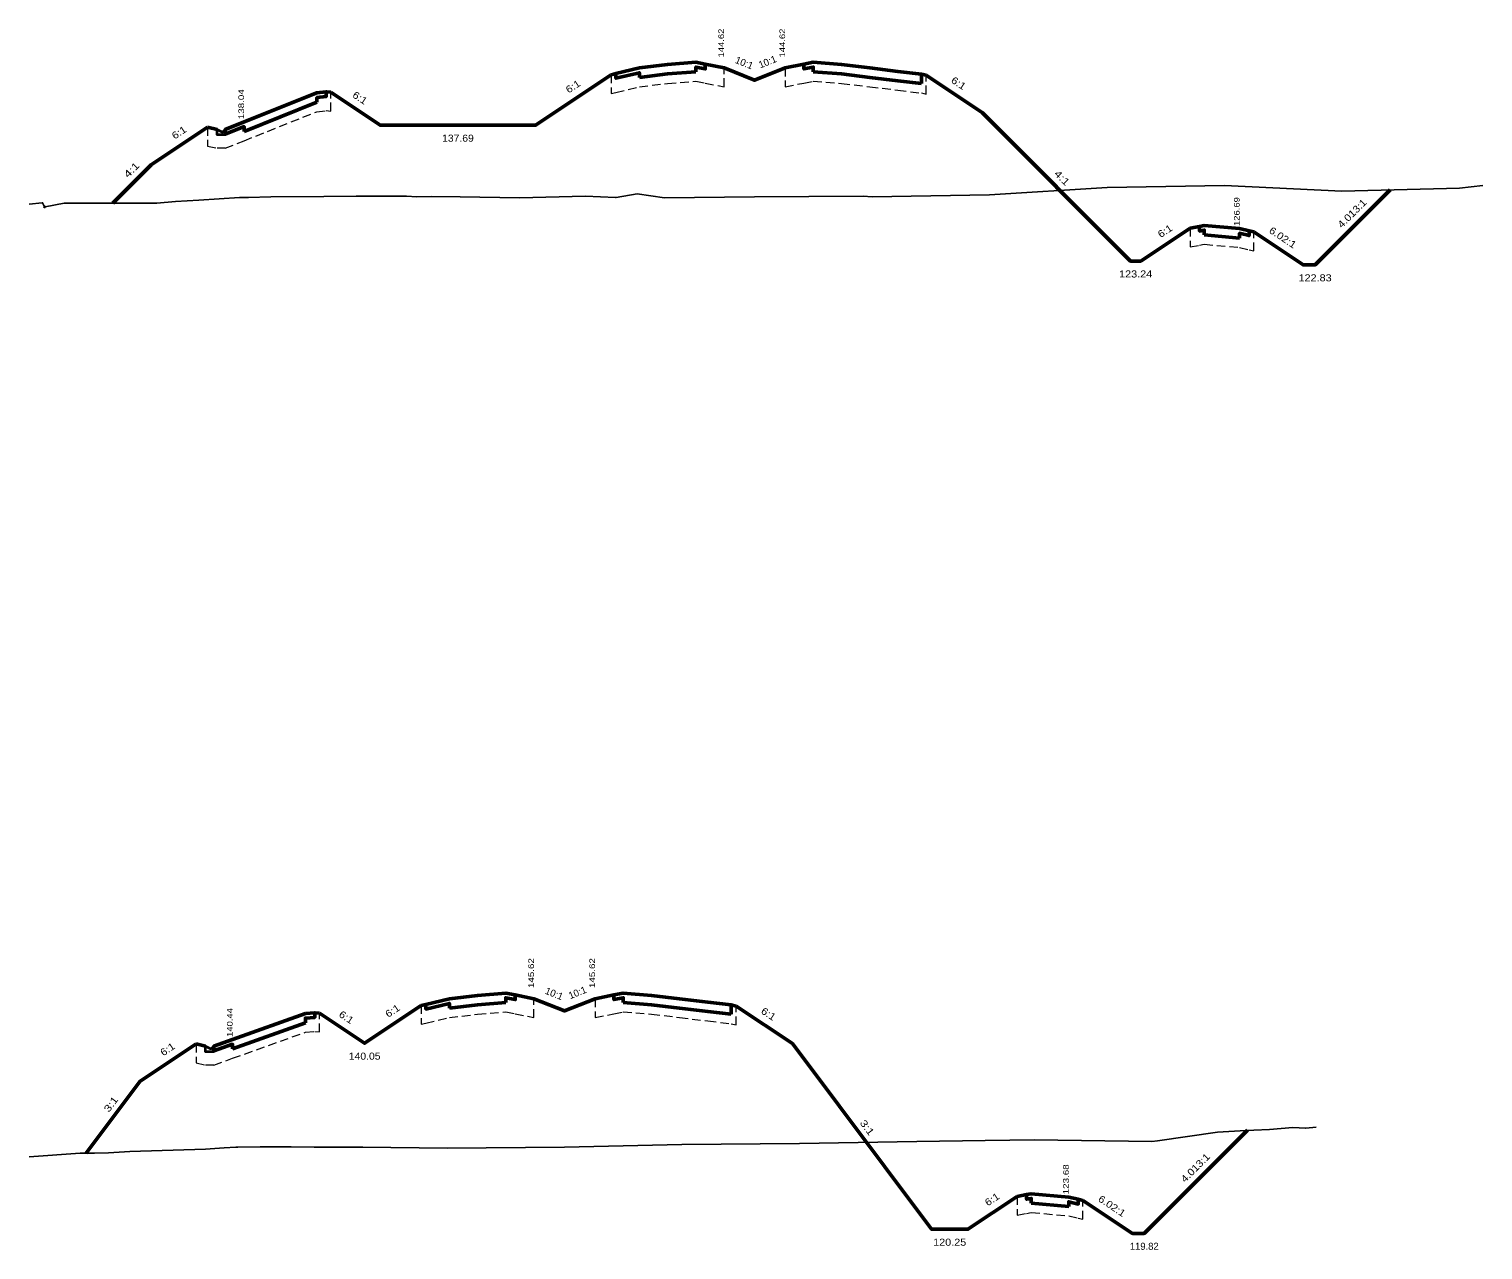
# Model space of a CAD drawing. Extents: x 72769 to 76375, y 67856 to 87579.
# Drawn here: x 72774 to 73393, y 87059 to 87579 of the extents above; entities that cross this region are included whole.
import ezdxf
from ezdxf.enums import TextEntityAlignment as Align

# ---------------------------------------------------------------- set-up
doc = ezdxf.new("R2010")
doc.units = 0
doc.header["$LTSCALE"] = 1.2
doc.header["$PDMODE"] = 32
doc.header["$PDSIZE"] = 0.6
doc.linetypes.add('MEDIUM_DASHED', pattern=[4.5, 3, -1.5])
for name, color, linetype, lineweight in [('1', 7, 'Continuous', 53), ('10', 7, 'Continuous', 53), ('11', 7, 'Continuous', 53), ('12', 7, 'Continuous', 53), ('13', 7, 'MEDIUM_DASHED', 13), ('61', 7, 'Continuous', 25)]:
    doc.layers.add(name, color=color, linetype=linetype, lineweight=lineweight)
for name, color, linetype in [('21', 7, 'Continuous'), ('50', 7, 'Continuous'), ('51', 7, 'Continuous'), ('52', 7, 'Continuous')]:
    doc.layers.add(name, color=color, linetype=linetype)

msp = doc.modelspace()

# ---------------------------------------------------------------- linework, layer by layer
at = {"layer": '1'}
for p, q in [((73034.074, 87562.069), (73046.076, 87563.509)), ((73034.074, 87558.069), (73046.076, 87559.509)), ((73046.076, 87563.509), (73058.076, 87564.469)), ((73046.076, 87559.509), (73058.076, 87560.469)), ((73108.077, 87564.469), (73120.075, 87563.509)), ((73108.077, 87560.469), (73120.075, 87559.509)), ((73120.075, 87563.509), (73132.075, 87562.069)), ((73120.075, 87559.509), (73132.075, 87558.069)), ((73132.075, 87562.069), (73144.075, 87560.629)), ((73144.075, 87560.629), (73154.076, 87559.429)), ((73132.075, 87558.069), (73144.075, 87556.629)), ((73144.075, 87556.629), (73154.076, 87555.429)), ((72865.784, 87539.098), (72896.785, 87551.469)), ((72865.784, 87535.098), (72896.785, 87547.469)), ((73274.47, 87495.068), (73289.521, 87493.721)), ((73274.47, 87491.068), (73289.521, 87489.721)), ((72953.175, 87166.069), (72965.177, 87167.509)), ((72953.175, 87162.069), (72965.177, 87163.509)), ((72965.177, 87167.509), (72977.176, 87168.469)), ((72965.177, 87163.509), (72977.176, 87164.469)), ((73027.177, 87168.469), (73039.176, 87167.509)), ((73027.177, 87164.469), (73039.176, 87163.509)), ((73039.176, 87167.509), (73051.176, 87166.069)), ((73039.176, 87163.509), (73051.176, 87162.069)), ((73051.176, 87166.069), (73063.176, 87164.629)), ((73063.176, 87164.629), (73073.177, 87163.429)), ((72860.901, 87148.708), (72891.903, 87159.801)), ((73051.176, 87162.069), (73063.176, 87160.629)), ((73063.176, 87160.629), (73073.177, 87159.429)), ((72860.901, 87144.708), (72891.903, 87155.801)), ((73200.855, 87083.109), (73216.808, 87081.681)), ((73200.855, 87079.109), (73216.808, 87077.681))]:
    msp.add_line(p, q, dxfattribs=at)
at = {"layer": '10'}
for p, q in [((73022.078, 87559.19), (73024.078, 87559.67)), ((73062.078, 87563.668), (73070.078, 87562.068)), ((73096.078, 87562.069), (73104.077, 87563.669)), ((73154.077, 87559.429), (73156.076, 87558.949)), ((72900.786, 87551.946), (72902.786, 87551.708)), ((72850.284, 87536.865), (72854.284, 87535.905)), ((73268.45, 87493.925), (73272.464, 87494.687)), ((73293.534, 87492.761), (73295.54, 87492.281)), ((72941.179, 87163.19), (72943.179, 87163.67)), ((72981.179, 87167.668), (72989.178, 87166.068)), ((73015.179, 87166.069), (73023.178, 87167.669)), ((73073.178, 87163.429), (73075.177, 87162.949)), ((72895.904, 87160.121), (72897.904, 87159.961)), ((72845.4, 87146.806), (72849.4, 87145.846)), ((73194.844, 87081.966), (73198.852, 87082.728)), ((73220.821, 87080.72), (73222.828, 87080.24))]:
    msp.add_line(p, q, dxfattribs=at)
at = {"layer": '10', "lineweight": 35}
for points in [[(72857.784, 87535.905), (72857.784, 87533.572), (72854.284, 87533.572), (72854.284, 87535.905), (72856.284, 87534.905), (72856.784, 87534.905)], [(72852.901, 87145.846), (72852.901, 87143.513), (72849.4, 87143.513), (72849.4, 87145.846), (72851.401, 87144.846), (72851.901, 87144.846)]]:
    msp.add_lwpolyline(points, close=True, dxfattribs=at)
at = {"layer": '11'}
for points in [[(73034.074, 87558.069), (73034.074, 87560.069), (73024.078, 87557.67), (73024.078, 87559.67), (73034.074, 87562.069)], [(73058.076, 87564.469), (73062.078, 87563.668), (73062.078, 87561.668), (73058.076, 87562.469), (73058.076, 87560.469)], [(73108.077, 87560.469), (73108.077, 87562.469), (73104.077, 87561.669), (73104.077, 87563.669), (73108.077, 87564.469)], [(73154.076, 87559.429), (73154.077, 87559.429), (73154.077, 87557.429), (73154.076, 87557.429), (73154.076, 87555.429)], [(72896.785, 87551.469), (72900.786, 87551.946), (72900.786, 87549.946), (72896.785, 87549.469), (72896.785, 87547.469)], [(72865.784, 87535.098), (72865.784, 87537.098), (72857.784, 87533.905), (72857.784, 87535.905), (72865.784, 87539.098)], [(73274.47, 87491.068), (73274.47, 87493.068), (73272.464, 87492.687), (73272.464, 87494.687), (73274.47, 87495.068)], [(73289.521, 87493.721), (73293.534, 87492.761), (73293.534, 87490.761), (73289.521, 87491.721), (73289.521, 87489.721)], [(72953.175, 87162.069), (72953.175, 87164.069), (72943.179, 87161.67), (72943.179, 87163.67), (72953.175, 87166.069)], [(72977.176, 87168.469), (72981.179, 87167.668), (72981.179, 87165.668), (72977.176, 87166.469), (72977.176, 87164.469)], [(73027.177, 87164.469), (73027.177, 87166.469), (73023.178, 87165.669), (73023.178, 87167.669), (73027.177, 87168.469)], [(73073.177, 87163.429), (73073.178, 87163.429), (73073.178, 87161.429), (73073.177, 87161.429), (73073.177, 87159.429)], [(72891.903, 87159.801), (72895.904, 87160.121), (72895.904, 87158.121), (72891.903, 87157.801), (72891.903, 87155.801)], [(72860.901, 87144.708), (72860.901, 87146.708), (72852.901, 87143.846), (72852.901, 87145.846), (72860.901, 87148.708)], [(73200.855, 87079.109), (73200.855, 87081.109), (73198.852, 87080.728), (73198.852, 87082.728), (73200.855, 87083.109)], [(73216.808, 87081.681), (73220.821, 87080.72), (73220.821, 87078.72), (73216.808, 87079.681), (73216.808, 87077.681)]]:
    msp.add_lwpolyline(points, dxfattribs=at)
at = {"layer": '12'}
for points in [[(72902.786, 87551.708), (72923.786, 87537.708), (72989.855, 87537.708), (73022.078, 87559.19)], [(73070.078, 87562.068), (73083.077, 87556.869), (73096.078, 87562.069)], [(73156.076, 87558.949), (73180.076, 87542.949), (73243.1, 87479.925), (73247.45, 87479.925), (73268.45, 87493.925)], [(72809.968, 87504.551), (72826.283, 87520.865), (72850.284, 87536.865)], [(73295.54, 87492.281), (73316.611, 87478.281), (73321.627, 87478.281), (73353.613, 87510.16)], [(72897.904, 87159.961), (72917.12, 87147.15), (72941.179, 87163.19)], [(72989.178, 87166.068), (73002.178, 87160.869), (73015.179, 87166.069)], [(73075.177, 87162.949), (73099.177, 87146.949), (73158.414, 87067.966), (73173.844, 87067.966), (73194.844, 87081.966)], [(72798.562, 87100.362), (72821.398, 87130.806), (72845.4, 87146.806)], [(73222.828, 87080.24), (73243.898, 87066.24), (73248.915, 87066.24), (73292.902, 87110.081)]]:
    msp.add_lwpolyline(points, dxfattribs=at)
at = {"layer": '13'}
for p, q in [((73024.078, 87551.67), (73034.074, 87554.069)), ((73034.074, 87554.069), (73046.076, 87555.509)), ((73046.076, 87555.509), (73058.076, 87556.469)), ((73058.076, 87556.469), (73062.078, 87555.668)), ((73104.077, 87555.669), (73108.077, 87556.469)), ((73108.077, 87556.469), (73120.075, 87555.509)), ((73120.075, 87555.509), (73132.075, 87554.069)), ((73132.075, 87554.069), (73144.075, 87552.629)), ((73144.075, 87552.629), (73154.076, 87551.429)), ((73154.076, 87551.429), (73154.077, 87551.429)), ((72865.784, 87531.098), (72896.785, 87543.469)), ((72896.785, 87543.469), (72900.786, 87543.946)), ((72857.784, 87527.905), (72865.784, 87531.098)), ((72857.784, 87527.905), (72854.284, 87527.905)), ((73272.464, 87486.687), (73274.47, 87487.068)), ((73274.47, 87487.068), (73289.521, 87485.721)), ((73289.521, 87485.721), (73293.534, 87484.761)), ((72943.179, 87155.67), (72953.175, 87158.069)), ((72953.175, 87158.069), (72965.177, 87159.509)), ((72965.177, 87159.509), (72977.176, 87160.469)), ((72977.176, 87160.469), (72981.179, 87159.668)), ((73023.178, 87159.669), (73027.177, 87160.469)), ((73027.177, 87160.469), (73039.176, 87159.509)), ((73039.176, 87159.509), (73051.176, 87158.069)), ((73051.176, 87158.069), (73063.176, 87156.629)), ((72860.901, 87140.708), (72891.903, 87151.801)), ((72891.903, 87151.801), (72895.904, 87152.121)), ((73063.176, 87156.629), (73073.177, 87155.429)), ((73073.177, 87155.429), (73073.178, 87155.429)), ((72852.901, 87137.846), (72860.901, 87140.708)), ((72852.901, 87137.846), (72849.4, 87137.846)), ((73198.852, 87074.728), (73200.855, 87075.109)), ((73200.855, 87075.109), (73216.808, 87073.681)), ((73216.808, 87073.681), (73220.821, 87072.72))]:
    msp.add_line(p, q, dxfattribs=at)
for points in [[(73022.078, 87559.19), (73022.078, 87551.19), (73024.078, 87551.67)], [(73062.078, 87555.668), (73070.078, 87554.068), (73070.078, 87562.068)], [(73096.078, 87562.069), (73096.078, 87554.069), (73104.077, 87555.669)], [(73154.077, 87551.429), (73156.076, 87550.949), (73156.076, 87558.949)], [(72900.786, 87543.946), (72902.786, 87543.708), (72902.786, 87551.708)], [(72850.284, 87536.865), (72850.284, 87528.865), (72854.284, 87527.905)], [(73268.45, 87493.925), (73268.45, 87485.925), (73272.464, 87486.687)], [(73293.534, 87484.761), (73295.54, 87484.281), (73295.54, 87492.281)], [(72941.179, 87163.19), (72941.179, 87155.19), (72943.179, 87155.67)], [(72981.179, 87159.668), (72989.178, 87158.068), (72989.178, 87166.068)], [(73015.179, 87166.069), (73015.179, 87158.069), (73023.178, 87159.669)], [(73073.178, 87155.429), (73075.177, 87154.949), (73075.177, 87162.949)], [(72895.904, 87152.121), (72897.904, 87151.961), (72897.904, 87159.961)], [(72845.4, 87146.806), (72845.4, 87138.806), (72849.4, 87137.846)], [(73194.844, 87081.966), (73194.844, 87073.966), (73198.852, 87074.728)], [(73220.821, 87072.72), (73222.828, 87072.24), (73222.828, 87080.24)]]:
    msp.add_lwpolyline(points, dxfattribs=at)
at = {"layer": '61'}
for points in [[(72780.881, 87502.949), (72781.066, 87502.985), (72789.222, 87504.489), (72789.684, 87504.548), (72790.221, 87504.568), (72795.651, 87504.603), (72816.883, 87504.526), (72828.71, 87504.523), (72836.611, 87505.231), (72846.497, 87505.888), (72863.868, 87506.949), (72863.941, 87506.949), (72867.653, 87507.025), (72877.129, 87507.212), (72899.792, 87507.367), (72913.552, 87507.513), (72920.88, 87507.535), (72934.593, 87507.486), (72934.894, 87507.481), (72939.345, 87507.309), (72945.584, 87507.363), (72957.719, 87507.273), (72983.078, 87506.865), (73011.131, 87507.539), (73023.925, 87506.949), (73024.149, 87506.945), (73033.078, 87508.469), (73044.761, 87506.797), (73083.077, 87507.269), (73129.293, 87507.487), (73133.078, 87507.269), (73183.078, 87508.069), (73233.078, 87511.269), (73283.078, 87512.069), (73333.077, 87509.669), (73383.077, 87510.865), (73393.078, 87512.069)], [(72774.287, 87504.068), (72779.818, 87504.736), (72780.016, 87504.731), (72780.701, 87503.303), (72780.867, 87502.949), (72780.881, 87502.949)], [(72774.287, 87098.76), (72796.042, 87100.351), (72798.992, 87100.363), (72799.815, 87100.362), (72802.147, 87100.374), (72808.057, 87100.545), (72817.207, 87101.003), (72849.351, 87102.056), (72857.26, 87102.662), (72862.258, 87102.949), (72863.148, 87102.949), (72872.647, 87103.034), (72885.876, 87103.079), (72895.67, 87102.903), (72900.967, 87102.902), (72907.553, 87102.925), (72915.792, 87102.949), (72916.383, 87102.949), (72952.178, 87102.469), (73002.178, 87102.865), (73052.179, 87104.069), (73102.179, 87104.469), (73152.178, 87105.269), (73181.275, 87105.734), (73202.178, 87106.069), (73252.178, 87105.269), (73254.506, 87105.601), (73280.178, 87109.269), (73292.159, 87110.052), (73295.509, 87110.182), (73302.178, 87110.469), (73312.178, 87111.269), (73317.556, 87110.998), (73317.759, 87110.949), (73322.106, 87111.446)]]:
    msp.add_lwpolyline(points, dxfattribs=at)
msp.add_point((72780.881, 87502.949), dxfattribs=at)

# ---------------------------------------------------------------- texts
at = {"layer": '21'}
for s, width, p in [(' 144.62', 1.25, (73070.075, 87565.429)), (' 144.62', 1.25, (73096.075, 87565.429)), (' 138.04', 1.3, (72865.785, 87539.098)), (' 126.69', 1.25, (73289.521, 87493.721)), (' 145.62', 1.3, (72989.176, 87169.429)), (' 145.62', 1.3, (73015.176, 87169.429)), (' 140.44', 1.25, (72860.901, 87148.708)), (' 123.68', 1.3, (73216.808, 87081.681))]:
    msp.add_text(s, height=2.4, rotation=90, dxfattribs=dict(at, width=width)).set_placement(p)
at = {"layer": '50'}
for rotation, p in [(338.199, (73078.135, 87562.846)), (21.801, (73089.135, 87563.292)), (338.199, (72997.235, 87166.846)), (21.801, (73008.236, 87167.292))]:
    msp.add_text('10:1', height=3, rotation=rotation, dxfattribs=at).set_placement(p, align=Align.CENTER)
for s, rotation, width, p in [('6:1', 33.69, 1.15, (73006.634, 87552.949)), ('6:1', 326.31, 1.15, (73169.073, 87554.34)), ('6:1', 326.31, 1.15, (72914.282, 87548.099)), ('6:1', 33.689, 1.15, (72838.951, 87533.366)), ('4:1', 44.999, 1.3, (72818.944, 87517.649)), ('4:1', 315, 1.3, (73212.891, 87514.257)), ('4.013:1', 44.904, 1.15, (73338.438, 87499.157)), ('6:1', 33.69, 1.15, (73258.618, 87491.425)), ('6.02:1', 326.398, 1.15, (73307.069, 87488.675)), ('6:1', 33.69, 1.15, (72929.817, 87159.67)), ('6:1', 326.31, 1.15, (72908.508, 87156.946)), ('6:1', 326.31, 1.15, (73088.174, 87158.34)), ('6:1', 33.688, 1.15, (72834.066, 87143.307)), ('3:1', 53.128, 1.25, (72810.339, 87120.279)), ('3:1', 306.87, 1.25, (73129.787, 87110.352)), ('4.013:1', 44.904, 1.15, (73271.726, 87093.097)), ('6:1', 33.69, 1.15, (73185.012, 87079.466)), ('6.02:1', 326.398, 1.15, (73234.357, 87076.635))]:
    msp.add_text(s, height=3, rotation=rotation, dxfattribs=dict(at, width=width)).set_placement(p, align=Align.CENTER)
at = {"layer": '51'}
for s, width, p in [('137.69', 1.1, (72956.82, 87530.708)), ('123.24', 1.15, (73245.275, 87472.925)), ('122.83', 1.15, (73321.644, 87471.281)), ('120.25', 1.15, (73166.129, 87060.966))]:
    msp.add_text(s, height=3, dxfattribs=dict(at, width=width)).set_placement(p, align=Align.CENTER)
msp.add_text('119.82', height=3, dxfattribs=at).set_placement((73248.932, 87059.24), align=Align.CENTER)
at = {"layer": '52', "width": 1.1}
msp.add_text('140.05', height=3, dxfattribs=at).set_placement((72917.12, 87140.15), align=Align.CENTER)

doc.saveas('drawing.dxf')
